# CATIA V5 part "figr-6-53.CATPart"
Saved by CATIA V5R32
Part number: Part1
Bounding box of the stored display mesh (mm): x -46.66 to 43.071, y -43.071 to 47.059, z 0 to 20
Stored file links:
  D:\PROJECTS\Project 2022\CATIA V5 6R 2022\Resources\Part Files\c06_catia_v5_6r2022_prt\figr-6-53.CATPart
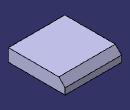
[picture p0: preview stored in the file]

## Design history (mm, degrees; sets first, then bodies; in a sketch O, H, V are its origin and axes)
Body1 (main body)
  Sketch1 on xy-plane, origin (0, 0, 0), H (1, 0, 0), V (0, 1, 0)
    line L1 (-46.6598, 47.0586) -> (43.0706, 47.0586)
    line L2 (43.0706, 47.0586) -> (43.0706, -43.0706)
    line L3 (43.0706, -43.0706) -> (-46.6598, -43.0706)
    line L4 (-46.6598, -43.0706) -> (-46.6598, 47.0586)
    horizontal: L1 H, L3 H
    vertical: L2 V, L4 V
  Pad1: profile Sketch1, direction (0, 0, 1), length 20
  Chamfer1: length 10, angle 45, on edge [face of Pad1 | face of Pad1]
